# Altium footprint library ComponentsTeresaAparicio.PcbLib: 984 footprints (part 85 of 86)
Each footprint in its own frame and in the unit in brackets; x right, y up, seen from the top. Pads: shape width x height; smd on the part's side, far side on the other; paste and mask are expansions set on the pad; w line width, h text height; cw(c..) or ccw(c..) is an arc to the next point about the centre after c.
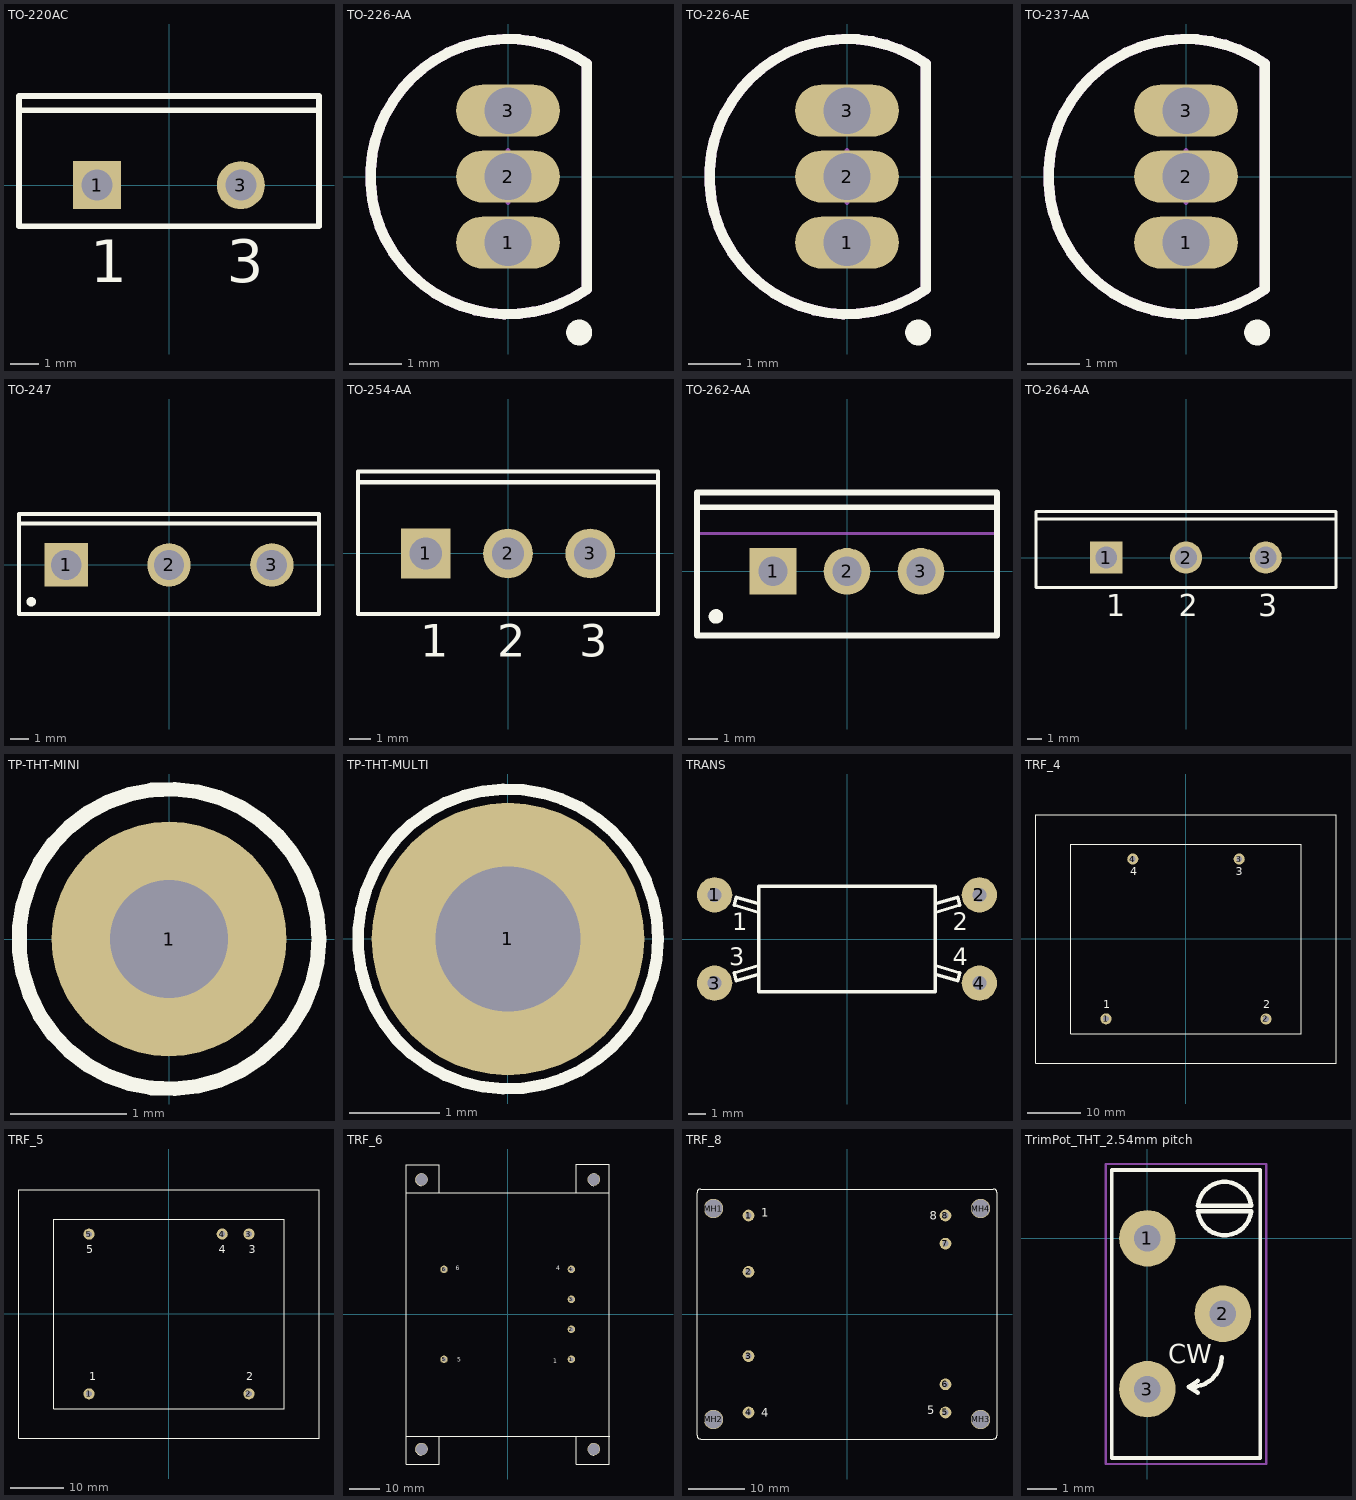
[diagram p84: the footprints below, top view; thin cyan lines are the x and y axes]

## TO-220AC [mm] "TO, Thru-Hole, Vertical, Heatsink Mounted; 3 In-Line Leads (1 Absent); Pitch 2.54 mm"
height 19.2
pads (2):
  rect 1.7x1.7 hole 1.1: 1(-2.54,0)
  round 1.7 hole 1.1: 3(2.54,0)
Top Overlay:
  lines w0.2: -5.3,2.65 5.3,2.65 ; -5.3,-1.45 -5.3,3.15 5.3,3.15 5.3,-1.45 -5.3,-1.45
  text "3" at 2.04,-3.425 h1.5
  text "1" at -2.79,-3.425 h1.5

## TO-226-AA [mm] "TO, Flat Index; 3 In-Line, Axial Leads; Body Dia. 4.8mm; Leads 0.55 x 0.51 mm (max)"
height 5.33
pads (3):
  oval 2x1 hole 0.9: 1(0,-1.27) 2(0,0) 3(0,1.27)
Top Overlay:
  circle w0.25: c1.371,-3.003 r0.125
  lines w0.2: 1.52,-2.171 cw(c0,0) 1.52,2.171 1.52,-2.171
Mechanical 13:
  lines w0.2: 1.52,-2.171 cw(c0,0) 1.52,2.171 1.52,-2.171
Mechanical 15:
  lines w0.1: -0.5,0 0.5,0 ; 0,-0.5 0,0.5
3D body: height 5.33, standoff 0, extent -2.659,-2.659 1.523,2.659

## TO-226-AE [mm] "TO, Flat Index; 3 In-Line, Axial Leads; Body Dia. 4.8mm; Leads 0.55 x 0.51 mm (max)"
height 7.87
pads (3):
  oval 2x1 hole 0.9: 1(0,-1.27) 2(0,0) 3(0,1.27)
Top Overlay:
  circle w0.25: c1.371,-3.003 r0.125
  lines w0.2: 1.52,-2.171 cw(c0,0) 1.52,2.171 1.52,-2.171
Mechanical 13:
  lines w0.2: 1.52,-2.171 cw(c0,0) 1.52,2.171 1.52,-2.171
Mechanical 15:
  lines w0.1: -0.5,0 0.5,0 ; 0,-0.5 0,0.5
3D body: height 7.87, standoff 0, extent -2.659,-2.659 1.523,2.659

## TO-237-AA [mm] "TO, Flat Index; 3 In-Line, Axial Leads; Body Dia. 4.8mm; Lead Dia. 0.56 mm (max)"
height 7.11
pads (3):
  oval 2x1 hole 0.9: 1(0,-1.27) 2(0,0) 3(0,1.27)
Top Overlay:
  circle w0.25: c1.371,-3.003 r0.125
  lines w0.2: 1.52,-2.171 cw(c0,0) 1.52,2.171 1.52,-2.171
Mechanical 13:
  lines w0.2: 1.52,-2.171 cw(c0,0) 1.52,2.171 1.52,-2.171
Mechanical 15:
  lines w0.1: -0.5,0 0.5,0 ; 0,-0.5 0,0.5
3D body: height 7.11, standoff 0, extent -2.659,-2.659 1.523,2.659

## TO-247 [mm] "SIP with Mounting Hole; 3 Leads; Body 20 x 15.6 x 5 mm (typ); Pitch 5.45 mm"
height 24.6
pads (3):
  rect 2.3x2.3 hole 1.6: 1(-5.45,0)
  round 2.3 hole 1.6: 2(0,0) 3(5.45,0)
Top Overlay:
  circle w0.25: c-7.3,-1.95 r0.125
  lines w0.2: -7.95,2.2 7.95,2.2 ; -7.95,-2.6 7.95,-2.6 7.95,2.7 -7.95,2.7 -7.95,-2.6
Mechanical 13:
  lines w0.1: -7.95,-2.6 7.95,-2.6 7.95,2.7 -7.95,2.7 -7.95,-2.6
Mechanical 15:
  lines w0.1: -0.5,0 0.5,0 ; 0,-0.5 0,0.5
3D body: height 24.6, standoff 3.7, extent -7.949,-2.599 7.949,2.699

## TO-254-AA [mm] "TO, Thru-Hole, Vertical, Heatsink Mounted; 3 In-Line Leads; Pitch 3.81 mm"
height 20.3
pads (3):
  rect 2.3x2.3 hole 1.5: 1(-3.81,0)
  round 2.3 hole 1.5: 2(0,0) 3(3.81,0)
Top Overlay:
  lines w0.2: -6.95,3.3 6.95,3.3 ; -6.95,-2.8 -6.95,3.8 6.95,3.8 6.95,-2.8 -6.95,-2.8
  text "3" at 3.31,-4.775 h1.5
  text "2" at -0.5,-4.775 h1.5
  text "1" at -4.06,-4.775 h1.5

## TO-262-AA [mm] "TO, Thru-Hole, Vertical, Heatsink Mounted; 3 In-Line Leads; Pitch 2.54 mm"
height 19.7
pads (3):
  rect 1.6x1.6 hole 1: 1(-2.54,0)
  round 1.6 hole 1: 2(0,0) 3(2.54,0)
Top Overlay:
  circle w0.25: c-4.5,-1.55 r0.125
  lines w0.2: -5.15,2.2 5.15,2.2 ; -5.15,-2.2 -5.15,2.7 5.15,2.7 5.15,-2.2 -5.15,-2.2
Mechanical 13:
  lines w0.1: -5.15,1.3 5.15,1.3 ; -5.15,-2.2 -5.15,2.7 5.15,2.7 5.15,-2.2 -5.15,-2.2
Mechanical 15:
  lines w0.1: -0.5,0 0.5,0 ; 0,-0.5 0,0.5
3D body: height 19.7, standoff 13.7, extent -5.149,1.301 5.149,2.699
3D body: height 13.7, standoff 2.8, extent -5.2,-2.25 5.2,2.75

## TO-264-AA [mm] "SIP with Mounting Hole; 3 Leads; Body 26 x 20 x 5 mm (typ); Pitch 5.45 mm"
height 29
pads (3):
  rect 2.2x2.2 hole 1.5: 1(-5.45,0)
  round 2.2 hole 1.5: 2(0,0) 3(5.45,0)
Top Overlay:
  lines w0.2: -10.25,2.65 10.25,2.65 ; -10.25,-2.05 -10.25,3.15 10.25,3.15 10.25,-2.05 -10.25,-2.05
  text "3" at 4.942,-4.025 h1.5
  text "2" at -0.508,-4.025 h1.5
  text "1" at -5.45,-4.025 h1.5
Mechanical 15:
  lines w0.1: -0.5,0 0.5,0 ; 0,-0.5 0,0.5

## TP-THT-MINI [mil] "Thru-hole test point loop"
height 181.1
pads (1):
  round 80 / inner round 80 / far side round 90 hole 40: 1(0,0)
Top Overlay:
  circle w5: c0,0 r51
Mechanical 13:
  circle w3: c0,0 r29.94
3D body: height 180.51, standoff -118.14, extent -48.82,-49.11 49.21,49.12

## TP-THT-MULTI [mm] "Thru-hole test point loop"
height 8.1
pads (1):
  round 3 hole 1.6: 1(0,0)
Top Overlay:
  circle w0.127: c0,0 r1.651
Mechanical 13:
  circle w0.076: c0,0 r0.76
3D body: height 8.09, standoff -3.21, extent -1.597,-1.6 1.597,1.587

## TRANS [mm] "Transformer; 4 Leads"
pads (4):
  round 2 hole 0.8: 1(-7.5,2.5) 2(7.5,2.5) 3(-7.5,-2.5) 4(7.5,-2.5)
Top Overlay:
  lines w0.2: -5,-2 -6.275,-2.375 -6.4,-1.925 -5,-1.5 ; -5,1.5 -6.4,1.925 -6.275,2.375 -5,2 ; 5,-2 6.275,-2.375 6.4,-1.925 5,-1.5 ; 5,1.5 6.4,1.925 6.275,2.375 5,2 ; -5,-3 5,-3 5,3 -5,3 -5,-3
  text "1" at -6.5,0.5 h1
  text "2" at 6,0.5 h1
  text "3" at -6.675,-1.5 h1
  text "4" at 6,-1.5 h1

## TRF_4 [mil] "Transformer; 4 Leads"
pads (4):
  round 82 hole 42: 1(-590.83,-590) 2(590.83,-590.83) 3(393.33,590.83) 4(-393.33,590.83)
Top Overlay:
  lines w8: -1108.33,-916.67 -1108.33,916.67 1108.33,916.67 1108.33,-916.67 -1108.33,-916.67 ; -850,-700 850,-700 850,700 -850,700 -850,-700
  text "3" at 369.17,470 h59.06
  text "4" at -410.83,470 h59.06
  text "2" at 569.17,-510 h59.06
  text "1" at -610.83,-510 h59.06

## TRF_5 [mil] "Transformer; 5 Leads"
pads (5):
  round 82 hole 42: 1(-590.83,-590.42) 2(590.83,-590.42) 3(590.83,590.42) 4(393.33,590.42) 5(-590.83,589.58)
Top Overlay:
  lines w8: -1108.33,-917.08 -1108.33,916.25 1108.33,916.25 1108.33,-917.08 -1108.33,-917.08 ; -850,-700.42 850,-700.42 850,699.58 -850,699.58 -850,-700.42
  text "5" at -610.83,449.58 h59.06
  text "1" at -590.83,-490.42 h59.06
  text "4" at 369.17,449.58 h59.06
  text "3" at 589.17,449.58 h59.06
  text "2" at 569.17,-490.42 h59.06

## TRF_6 [mil] "Transformer; 6 Leads"
pads (10):
  round 98 hole 52: 1(836.67,-590.83) 2(836.67,-196.67) 3(836.67,196.67) 4(836.67,590.83) 5(-836.67,-590.83) 6(-836.67,590.83)
  round 165 hole 152: MH1(-1131.67,-1771.67) MH2(1131.67,-1771.67) MH3(1131.67,1771.67) MH4(-1131.67,1771.67)
Top Overlay:
  lines w8: -1333.33,-1600 1341.67,-1600 ; -1333.33,1600 1333.33,1600 ; -1133.33,-1850 cw(c-1133.33,-1775) -1133.33,-1700 ; -1133.33,1691.67 cw(c-1133.33,1766.67) -1133.33,1841.67 ; -900,-1600 -900,-1966.67 -1333.33,-1966.67 -1333.33,1966.67 -900,1966.67 -900,1600 ; 900,-1600 900,-1966.67 1333.33,-1966.67 1333.33,1966.67 ; 900,1600 900,1975 1333.33,1975 ; 1133.33,-1850 cw(c1133.33,-1775) 1133.33,-1700 ; 1133.33,1691.67 cw(c1133.33,1766.67) 1133.33,1841.67
  text "6" at -680,580 h59.06
  text "4" at 640,580 h59.06
  text "1" at 600,-640 h59.06
  text "5" at -660,-620 h59.06

## TRF_8 [mil] "Transformer; 8 Leads"
pads (12):
  round 82 hole 42: 1(-689.17,689.17) 2(-689.17,295) 3(-689.17,-295) 4(-689.17,-689.17) 5(689.17,-689.17) 6(689.17,-492.5) 7(689.17,492.5) 8(689.17,689.17)
  round 135 hole 125: MH1(-935,738.33) MH2(-935,-738.33) MH3(935,-738.33) MH4(935,738.33)
Top Overlay:
  lines w8: -1050,-850 ccw(c-1025,-850) -1025,-875 1025,-875 ccw(c1025,-850) 1050,-850 1050,850 ccw(c1025,850) 1025,875 -1025,875 ccw(c-1025,850) -1050,850 -1050,-850
  text "1" at -600,680 h59.06
  text "5" at 560,-700 h59.06
  text "8" at 580,660 h59.06
  text "4" at -600,-720 h59.06

## TrimPot_THT_2.54mm pitch [mil] "TRIMMER, MURATA, PV36Y"
height 421.26
pads (3):
  round 75 hole 35: 1(0,0) 2(100,-100) 3(0,-200)
Top Overlay:
  lines w5: -47.24,-291.34 -47.24,90.55 149.61,90.55 149.61,-291.34 -47.24,-291.34
  lines w6: 58.86,-197.05 ccw(c58.86,-157.48) 98.43,-157.48 ; 66.93,-204.72 55.12,-197.05 66.93,-188.98 ; 67.07,35.81 137.65,35.81 ; 67.06,43.31 137.66,43.31 ; 67.12,43.3 cw(c102.36,39.55) 137.6,43.3 ; 67.13,35.81 ccw(c102.36,39.55) 137.59,35.81
  text "CW" at 27.56,-165.35 h25
Mechanical 13:
  lines w3: -47.24,-291.34 -47.24,90.55 149.61,90.55 149.61,-291.34 -47.24,-291.34
Mechanical 14:
  lines w3: -30,0 30,0 ; 0,-30 0,30 ; -55.12,-299.34 157.48,-299.34 157.48,98.66 -55.12,98.66 -55.12,-299.34
3D body: height 444.88, standoff -236.22, extent -47.24,-287.4 149.61,90.55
